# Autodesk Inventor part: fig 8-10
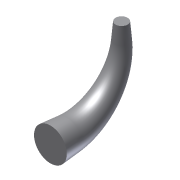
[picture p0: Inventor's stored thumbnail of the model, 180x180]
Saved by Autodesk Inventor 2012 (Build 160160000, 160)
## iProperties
Shininess: 77.0
Length Units: 11269
Angle Units: 11279
Time Units: 11290
Mass Units: 11283
Length Display Precision: 3
Angle Display Precision: 2
Created: 2001-12
Part Number: fig 8-10
Document SubType Name: Modeling
Designer: CADSoft
Density: 1 g/cm^3
Material: Default
Density: 0.0
Volumn: 0.0
Area: 0.0
PropertySet Name: Model Information
Control State: 0
Master: False
Checked Out: False
Author: CADSoft
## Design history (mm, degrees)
sketch "Sketch6"
  geometry: L1 (-48.928, -34.062)-(-33.928, -34.062); L2 (16.072, 15.938)-(16.072, 30.938); A1 r 50 centre (-33.928, 15.938) between (-33.928, -34.062) and (16.072, 15.938)
  constraints: 4 end point, 2 point on circle, 2 tangent, 1 centre point, 1 horizontal, 1 perpendicular
  dimensions: "d4" = 15 distance of L1.start L1.end; "d5" = 15 distance of L2.start L2.end; "d6" = 50 radius of A1
workplane "Work Plane1"
sketch "Sketch7"
  geometry: C1 r 15 at (0, 0)
  constraints: 1 centre point
  dimensions: "d7" = 30 diameter of C1
sweep "Sweep7" sketch "Sketch7" dims "d13" = -5 deg
body "Solid1"
